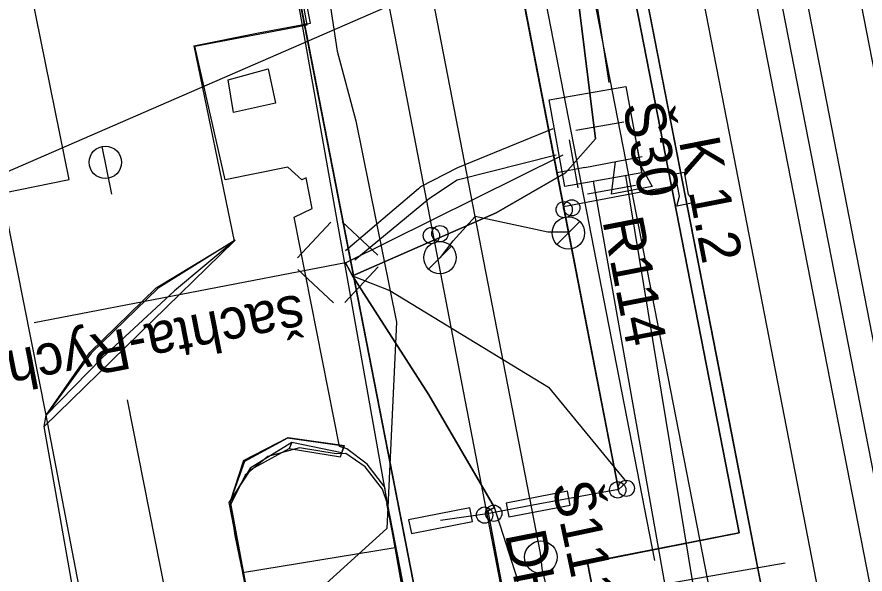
# Model space of a CAD drawing. Extents: x -545736 to -544888, y -1122892 to -1119128.
# Drawn here: x -545210.15 to -545184.08, y -1121953.8 to -1121936.67 of the extents above; entities that cross this region are included whole.
import ezdxf

# ---------------------------------------------------------------- set-up
doc = ezdxf.new("R2010")
doc.units = 0
for name, color, linetype in [('osvětlené plochy-hodnota-obrys', 7, 'Continuous'), ('Podbarveni_Nastupiste', 7, 'Continuous'), ('Podbarveni_Zastreseni_Pozemni', 7, 'Continuous'), ('Vrstva 1 - Koleje', 7, 'Continuous'), ('Vrstva 12', 7, 'Continuous'), ('Vrstva 14_zastreseni a nastupiste', 7, 'Continuous'), ('Vrstva 16_plochy', 7, 'Continuous'), ('Vrstva 17', 7, 'Continuous'), ('Vrstva 23', 7, 'Continuous'), ('Vrstva 28 - zabzar', 7, 'Continuous'), ('Vrstva 29 - sdelzar', 7, 'Continuous'), ('Vrstva 31', 7, 'Continuous'), ('Vrstva 33 - prvky sdelzar', 7, 'Continuous'), ('Vrstva 34', 7, 'Continuous'), ('Vrstva 35', 7, 'Continuous'), ('Vrstva 36', 7, 'Continuous'), ('Vrstva 4 - Teren - stezky - prechody - plochy', 7, 'Continuous'), ('Vrstva 42', 7, 'Continuous'), ('Vrstva 43', 7, 'Continuous'), ('Vrstva 44', 7, 'Continuous'), ('Vrstva 63', 7, 'Continuous')]:
    doc.layers.add(name, color=color, linetype=linetype)

msp = doc.modelspace()

# ---------------------------------------------------------------- linework, layer by layer
at = {"layer": 'osvětlené plochy-hodnota-obrys'}
msp.add_lwpolyline([(-545132.033, -1122317.745), (-545201.844, -1121957.194), (-545188.779, -1121954.655), (-545199.189, -1121901.389)], dxfattribs=at)
at = {"layer": 'Podbarveni_Nastupiste'}
for points in [[(-545187.251, -1121954.256), (-545197.191, -1121903.223), (-545206.675, -1121854.601), (-545216.326, -1121805.1), (-545225.795, -1121756.548), (-545231.585, -1121726.856)], [(-545208.774, -1121898.648), (-545202.231, -1121932.191), (-545198.773, -1121951.627)], [(-545198.773, -1121951.627), (-545191.691, -1121987.986), (-545182.222, -1122036.609), (-545172.438, -1122086.699), (-545162.999, -1122135.094), (-545153.274, -1122184.937), (-545142.505, -1122240.181), (-545142.306, -1122241.006)]]:
    msp.add_lwpolyline(points, dxfattribs=at)
at = {"layer": 'Podbarveni_Zastreseni_Pozemni'}
for p, q in [((-545192.608, -1121953.452), (-545187.955, -1121952.531)), ((-545192.612, -1121953.456), (-545192.608, -1121953.452))]:
    msp.add_line(p, q, dxfattribs=at)
for points in [[(-545187.955, -1121952.531), (-545197.581, -1121903.153), (-545207.045, -1121854.61), (-545216.686, -1121805.155), (-545226.175, -1121756.48), (-545231.934, -1121726.937)], [(-545208.774, -1121898.648), (-545202.231, -1121932.191), (-545197.881, -1121954.495)], [(-545183.384, -1122000.766), (-545186.124, -1121986.718), (-545192.612, -1121953.456)]]:
    msp.add_lwpolyline(points, dxfattribs=at)
at = {"layer": 'Vrstva 1 - Koleje'}
for points in [[(-545190.577, -1121928.351), (-545188.26, -1121940.241), (-545186.358, -1121950.008), (-545185.594, -1121953.976), (-545183.573, -1121964.342), (-545182.039, -1121972.211), (-545181.093, -1121977.067), (-545180.755, -1121978.799)], [(-545185.695, -1121928.619), (-545183.788, -1121938.392), (-545181.884, -1121948.167), (-545179.964, -1121958.007), (-545178.054, -1121967.8), (-545176.139, -1121977.604), (-545175.527, -1121980.741), (-545173.78, -1121989.695), (-545172.335, -1121997.117), (-545170.423, -1122006.932), (-545168.989, -1122014.279), (-545168.521, -1122016.677), (-545168.51, -1122016.735), (-545167.951, -1122019.64), (-545166.744, -1122025.83), (-545165.674, -1122031.328), (-545164.107, -1122039.354), (-545162.631, -1122046.922), (-545161.94, -1122050.474), (-545160.406, -1122058.34), (-545159.059, -1122065.253), (-545158.132, -1122070.002), (-545157.157, -1122074.99), (-545153.328, -1122094.638)]]:
    msp.add_lwpolyline(points, dxfattribs=at)
at = {"layer": 'Vrstva 12'}
for p, q in [((-545201.833, -1121949.62), (-545201.813, -1121949.606)), ((-545201.708, -1121949.757), (-545201.787, -1121949.944)), ((-545200.21, -1121950.201), (-545200.086, -1121949.848)), ((-545200.102, -1121949.872), (-545200.086, -1121949.848)), ((-545203.191, -1121950.312), (-545203.602, -1121951.576)), ((-545203.154, -1121950.338), (-545203.191, -1121950.312)), ((-545202.981, -1121950.545), (-545202.961, -1121950.588)), ((-545203.602, -1121951.576), (-545203.632, -1121951.602))]:
    msp.add_line(p, q, dxfattribs=at)
for points in [[(-545202.201, -1121939.318), (-545203.499, -1121939.609), (-545203.66, -1121938.6), (-545202.434, -1121938.261)], [(-545200.164, -1121950.073), (-545200.102, -1121949.872), (-545201.833, -1121949.62), (-545203.154, -1121950.338), (-545203.602, -1121951.576), (-545202.869, -1121955.481), (-545202.858, -1121955.552), (-545202.768, -1121956.297), (-545202.706, -1121956.342), (-545203.632, -1121951.602), (-545202.961, -1121950.588), (-545201.787, -1121949.944), (-545200.21, -1121950.201)]]:
    msp.add_lwpolyline(points, close=True, dxfattribs=at)
for points in [[(-545203.448, -1121943.531), (-545203.448, -1121943.531), (-545205.814, -1121945.005), (-545207.869, -1121947.007), (-545209.259, -1121948.92), (-545207.916, -1121946.985), (-545205.876, -1121944.997), (-545203.448, -1121943.531)], [(-545203.448, -1121943.531), (-545205.311, -1121945.094), (-545207.53, -1121947.153), (-545209.259, -1121948.92)], [(-545203.191, -1121950.312), (-545201.813, -1121949.606), (-545200.086, -1121949.848)], [(-545200.164, -1121950.073), (-545201.708, -1121949.757), (-545202.981, -1121950.545), (-545203.602, -1121951.576)]]:
    msp.add_lwpolyline(points, dxfattribs=at)
at = {"layer": 'Vrstva 14_zastreseni a nastupiste'}
msp.add_line((-545192.612, -1121953.456), (-545192.608, -1121953.452), dxfattribs=at)
for points in [[(-545187.955, -1121952.531), (-545197.617, -1121902.959), (-545207.134, -1121854.134), (-545216.759, -1121804.75), (-545226.215, -1121756.237), (-545235.472, -1121708.744), (-545235.481, -1121708.743), (-545226.175, -1121756.48), (-545216.686, -1121805.155), (-545207.045, -1121854.61), (-545197.581, -1121903.153), (-545187.955, -1121952.532)], [(-545197.884, -1121954.495), (-545202.248, -1121932.117), (-545208.774, -1121898.648), (-545208.774, -1121898.648), (-545202.231, -1121932.191), (-545197.881, -1121954.495)], [(-545187.251, -1121954.256), (-545188.391, -1121948.391), (-545190.303, -1121938.581), (-545192.214, -1121928.77)], [(-545187.245, -1121954.27), (-545188.385, -1121948.405), (-545190.297, -1121938.595), (-545192.208, -1121928.784)], [(-545198.773, -1121951.627), (-545198.793, -1121951.631), (-545197.668, -1121957.434), (-545195.753, -1121967.224), (-545195.374, -1121969.187), (-545193.463, -1121979.015), (-545191.56, -1121988.764), (-545189.639, -1121998.596), (-545187.731, -1122008.385), (-545185.791, -1122018.31), (-545183.91, -1122027.957), (-545182.003, -1122037.734), (-545180.094, -1122047.536), (-545178.189, -1122057.285), (-545176.275, -1122067.11), (-545174.372, -1122076.877), (-545172.469, -1122086.648)], [(-545198.773, -1121951.627), (-545197.637, -1121957.485), (-545195.722, -1121967.275), (-545195.343, -1121969.238), (-545193.432, -1121979.066), (-545191.529, -1121988.815), (-545189.608, -1121998.647), (-545187.7, -1122008.436), (-545185.76, -1122018.361), (-545183.879, -1122028.008), (-545181.972, -1122037.785), (-545180.063, -1122047.587), (-545178.158, -1122057.336), (-545176.244, -1122067.161), (-545174.341, -1122076.928), (-545172.438, -1122086.699)], [(-545192.612, -1121953.456), (-545191.169, -1121953.17), (-545187.955, -1121952.531), (-545187.955, -1121952.532), (-545192.608, -1121953.452)], [(-545138.248, -1122232.184), (-545147.826, -1122183.078), (-545157.444, -1122133.764), (-545166.966, -1122084.945), (-545176.486, -1122036.133), (-545186.124, -1121986.718), (-545192.612, -1121953.456)], [(-545192.608, -1121953.452), (-545186.031, -1121987.181), (-545176.442, -1122036.358), (-545166.925, -1122085.165), (-545157.406, -1122133.984), (-545147.796, -1122183.265), (-545138.257, -1122232.186)]]:
    msp.add_lwpolyline(points, dxfattribs=at)
for centre in [(-545193.33, -1121942.594), (-545193.096, -1121942.538), (-545197.412, -1121943.393), (-545197.15, -1121943.334), (-545191.684, -1121951.215), (-545191.422, -1121951.166), (-545195.776, -1121951.99), (-545195.495, -1121951.933)]:
    msp.add_circle(centre, 0.25, dxfattribs=at)
at = {"layer": 'Vrstva 16_plochy'}
for points in [[(-545198.772, -1121951.626), (-545198.846, -1121951.132), (-545199.386, -1121950.421), (-545200.013, -1121949.951), (-545200.237, -1121949.881), (-545201.629, -1121942.821), (-545201.074, -1121942.555), (-545201.266, -1121941.615), (-545201.396, -1121941.674), (-545201.822, -1121941.29), (-545203.751, -1121941.677), (-545204.686, -1121937.57), (-545201.23, -1121936.907), (-545202.884, -1121927.9), (-545206.444, -1121928.549), (-545207.952, -1121920.539), (-545208.311, -1121918.602), (-545208.161, -1121917.406), (-545206.384, -1121916.999), (-545207.447, -1121909.391), (-545205.017, -1121908.98)], [(-545187.251, -1121954.256), (-545188.391, -1121948.391), (-545190.303, -1121938.581), (-545192.214, -1121928.77)], [(-545172.438, -1122086.699), (-545174.341, -1122076.928), (-545176.244, -1122067.161), (-545178.158, -1122057.336), (-545180.063, -1122047.587), (-545181.972, -1122037.785), (-545183.879, -1122028.008), (-545185.76, -1122018.361), (-545187.7, -1122008.436), (-545189.608, -1121998.647), (-545191.529, -1121988.815), (-545193.432, -1121979.066), (-545195.343, -1121969.238), (-545195.722, -1121967.275), (-545197.637, -1121957.485), (-545198.773, -1121951.627)]]:
    msp.add_lwpolyline(points, dxfattribs=at)
at = {"layer": 'Vrstva 17'}
for p, q in [((-545204.716, -1121937.552), (-545202.733, -1121937.156)), ((-545204.716, -1121937.552), (-545203.473, -1121943.564)), ((-545203.473, -1121943.564), (-545209.317, -1121949.263))]:
    msp.add_line(p, q, dxfattribs=at)
msp.add_lwpolyline([(-545202.733, -1121937.156), (-545201.132, -1121936.862), (-545202.894, -1121927.887), (-545206.444, -1121928.549)], dxfattribs=at)
at = {"layer": 'Vrstva 23'}
for p, q in [((-545203.434, -1121965.339), (-545206.752, -1121948.44)), ((-545196.366, -1122015.979), (-545209.259, -1121948.92))]:
    msp.add_line(p, q, dxfattribs=at)
msp.add_lwpolyline([(-545199.383, -1122000.837), (-545202.829, -1121983.168), (-545208.015, -1121956.626), (-545209.317, -1121949.263), (-545209.259, -1121948.92), (-545210.612, -1121942.089), (-545208.554, -1121941.671), (-545213.053, -1121919.523), (-545225.888, -1121922.128)], dxfattribs=at)
at = {"layer": 'Vrstva 28 - zabzar'}
msp.add_lwpolyline([(-545184.11, -1121980.06), (-545190.31, -1121981.59), (-545194.52, -1121959.69), (-545194.75, -1121953.99), (-545195.47, -1121951.76), (-545197.49, -1121948.29), (-545199.84, -1121944.63), (-545200.05, -1121944.23), (-545193.363, -1121940.913)], dxfattribs=at)
at = {"layer": 'Vrstva 29 - sdelzar'}
for p, q in [((-545192.69, -1121941.3), (-545193.55, -1121941.46)), ((-545190.48, -1121941.96), (-545193.35, -1121942.51)), ((-545191.66, -1121951.2), (-545191.41, -1121950.98)), ((-545195.72, -1121951.89), (-545195.47, -1121951.76)), ((-545195.72, -1121951.89), (-545195.7, -1121951.95)), ((-545170.88, -1122078.92), (-545195.7, -1121951.95))]:
    msp.add_line(p, q, dxfattribs=at)
for points in [[(-545238.22, -1121711.14), (-545234.93, -1121728.12), (-545231.3, -1121746.83), (-545227.7, -1121765.38), (-545223.97, -1121784.59), (-545220.37, -1121803.18), (-545216.73, -1121821.93), (-545213.13, -1121840.52), (-545209.71, -1121858.15), (-545206.26, -1121875.91), (-545203.14, -1121892.01), (-545203.04, -1121892.5), (-545200.17, -1121907.31), (-545196.87, -1121924.33), (-545191.66, -1121951.2)], [(-545191.66, -1121951.2), (-545193.35, -1121942.51), (-545235.14, -1121727)], [(-545225.37, -1121777.4), (-545216.94, -1121820.87), (-545205.32, -1121880.79), (-545201.375, -1121901.125), (-545191.66, -1121951.2), (-545194.13, -1121951.65), (-545195.7, -1121951.95), (-545197.13, -1121952.16)], [(-545141.59, -1122228.62), (-545144.06, -1122216.03), (-545147.37, -1122199.08), (-545150.66, -1122182.28), (-545153.96, -1122165.39), (-545157.26, -1122148.51), (-545160.57, -1122131.6), (-545163.89, -1122114.65), (-545167.28, -1122097.28), (-545170.47, -1122080.98), (-545173.77, -1122064.13), (-545177.12, -1122047.02), (-545180.38, -1122030.35), (-545180.51, -1122029.8), (-545183.68, -1122013.47), (-545187, -1121996.49), (-545190.31, -1121979.56), (-545193.64, -1121962.56), (-545195.18, -1121954.67), (-545202.44, -1121916.94)], [(-545195.67, -1121951.86), (-545195.68, -1121951.84), (-545195.47, -1121951.76)], [(-545144.46, -1122213.97), (-545194.03, -1121960.56), (-545195.67, -1121951.86)]]:
    msp.add_lwpolyline(points, dxfattribs=at)
at = {"layer": 'Vrstva 31'}
msp.add_line((-545200.05, -1121944.23), (-545209.63, -1121946.08), dxfattribs=at)
for points in [[(-545200.05, -1121944.23), (-545199.84, -1121944.63), (-545195.42, -1121942.69), (-545193.29, -1121941.46), (-545192.37, -1121940.42), (-545194.56, -1121922.72)], [(-545194.56, -1121922.72), (-545192.37, -1121940.42), (-545193.29, -1121941.46), (-545195.42, -1121942.69), (-545199.84, -1121944.63)], [(-545199.84, -1121944.63), (-545195.42, -1121942.69), (-545193.29, -1121941.46), (-545192.37, -1121940.42)], [(-545200.05, -1121944.23), (-545199.84, -1121944.63)], [(-545195.47, -1121951.76), (-545197.49, -1121948.29), (-545199.84, -1121944.63)], [(-545199.84, -1121944.63), (-545198.69, -1121945.08), (-545193.81, -1121948.05), (-545191.41, -1121950.98)], [(-545199.84, -1121944.63), (-545197.49, -1121948.29), (-545195.47, -1121951.76), (-545195.72, -1121951.89)], [(-545199.84, -1121944.63), (-545198.69, -1121945.08), (-545193.81, -1121948.05), (-545191.41, -1121950.98), (-545191.66, -1121951.2)], [(-545199.84, -1121944.63), (-545198.69, -1121945.08), (-545193.81, -1121948.05), (-545191.41, -1121950.98), (-545191.66, -1121951.2)], [(-545199.84, -1121944.63), (-545197.49, -1121948.29), (-545195.47, -1121951.76)]]:
    msp.add_lwpolyline(points, dxfattribs=at)
at = {"layer": 'Vrstva 33 - prvky sdelzar'}
for p, q in [((-545192.69, -1121941.3), (-545190.931, -1121940.959)), ((-545190.48, -1121941.96), (-545189.852, -1121941.838))]:
    msp.add_line(p, q, dxfattribs=at)
for points in [[(-545191.119, -1121940.995), (-545190.622, -1121941.877), (-545191.879, -1121942.121), (-545191.748, -1121941.117)], [(-545189.918, -1121941.496), (-545189.646, -1121941.443)], [(-545189.785, -1121942.18), (-545189.918, -1121941.496)], [(-545189.646, -1121941.443), (-545189.513, -1121942.127)], [(-545189.867, -1121942.484), (-545189.785, -1121942.18)], [(-545189.513, -1121942.127), (-545189.318, -1121942.377)], [(-545189.318, -1121942.377), (-545189.867, -1121942.484)]]:
    msp.add_lwpolyline(points, dxfattribs=at)
for points in [[(-545193.147, -1121951.679), (-545193.231, -1121951.254), (-545195.112, -1121951.622), (-545195.029, -1121952.047)], [(-545196.147, -1121952.189), (-545196.231, -1121951.764), (-545198.112, -1121952.132), (-545198.029, -1121952.557)]]:
    msp.add_lwpolyline(points, close=True, dxfattribs=at)
at = {"layer": 'Vrstva 34'}
for p, q in [((-545192.97, -1121940.154), (-545191.494, -1121939.888)), ((-545191.203, -1121940.089), (-545190.937, -1121941.565)), ((-545192.905, -1121941.921), (-545193.171, -1121940.445)), ((-545191.138, -1121941.856), (-545192.614, -1121942.122)), ((-545200.153, -1121942.972), (-545199.057, -1121943.997)), ((-545201.531, -1121944.08), (-545200.506, -1121942.984)), ((-545200.423, -1121945.458), (-545201.519, -1121944.433)), ((-545199.045, -1121944.35), (-545200.07, -1121945.446))]:
    msp.add_line(p, q, dxfattribs=at)
at = {"layer": 'Vrstva 35'}
for points in [[(-545191.944, -1121938.683), (-545195.619, -1121914.8)], [(-545193.678, -1121940.11), (-545196.608, -1121941.311), (-545197.744, -1121941.897), (-545197.809, -1121941.954), (-545200.056, -1121943.857)], [(-545193.578, -1121940.922), (-545196.616, -1121941.684), (-545197.468, -1121942.254), (-545199.768, -1121944.147)], [(-545184.906, -1121977.25), (-545187.86, -1121963.28), (-545191.432, -1121941.547)], [(-545185.989, -1121977.456), (-545188.56, -1121963.51), (-545192.424, -1121941.723)]]:
    msp.add_lwpolyline(points, dxfattribs=at)
at = {"layer": 'Vrstva 36'}
msp.add_lwpolyline([(-545193.79, -1121939.22), (-545191.43, -1121938.81), (-545190.94, -1121941.46), (-545193.31, -1121941.88)], close=True, dxfattribs=at)
for points in [[(-545193.79, -1121939.22), (-545191.43, -1121938.81), (-545190.94, -1121941.46), (-545193.31, -1121941.88), (-545193.79, -1121939.22)], [(-545191.43, -1121938.81), (-545191.43, -1121938.81)], [(-545193.79, -1121939.22), (-545193.79, -1121939.22)], [(-545190.94, -1121941.46), (-545190.94, -1121941.46)], [(-545193.31, -1121941.88), (-545193.31, -1121941.88)]]:
    msp.add_lwpolyline(points, dxfattribs=at)
at = {"layer": 'Vrstva 4 - Teren - stezky - prechody - plochy'}
msp.add_line((-545191.456, -1121954.323), (-545186.532, -1121953.455), dxfattribs=at)
for points in [[(-545168.578, -1122024.344), (-545174.628, -1121993.69), (-545179.747, -1121967.537), (-545186.346, -1121933.692), (-545192.541, -1121901.817), (-545198.719, -1121870.005), (-545203.649, -1121844.746)], [(-545168.578, -1122024.344), (-545170.138, -1122024.197), (-545176.818, -1121990.692), (-545181.528, -1121966.416), (-545187.742, -1121934.55), (-545194.141, -1121901.786), (-545200.392, -1121870.233)], [(-545187.245, -1121954.27), (-545188.385, -1121948.405), (-545190.297, -1121938.595), (-545192.208, -1121928.784)], [(-545191.56, -1121988.764), (-545193.463, -1121979.015), (-545195.374, -1121969.187), (-545195.753, -1121967.224), (-545197.668, -1121957.434), (-545198.305, -1121954.272), (-545198.526, -1121952.983), (-545198.777, -1121951.611), (-545198.918, -1121951.188), (-545199.444, -1121950.503), (-545200.046, -1121950.093), (-545200.336, -1121950.101), (-545201.47, -1121949.918), (-545202.442, -1121950.189), (-545203.141, -1121950.759), (-545203.59, -1121951.67), (-545203.458, -1121952.616), (-545203.219, -1121953.758), (-545202.906, -1121955.205), (-545202.565, -1121956.903)], [(-545203.219, -1121953.758), (-545198.526, -1121952.983)]]:
    msp.add_lwpolyline(points, dxfattribs=at)
at = {"layer": 'Vrstva 42'}
for points in [[(-545203.534, -1121918.02), (-545203.421, -1121918.681), (-545202.986, -1121920.789), (-545201.955, -1121926.819), (-545200.311, -1121937.722)], [(-545200.311, -1121937.722), (-545199.74, -1121939.864), (-545198.486, -1121946.055), (-545198.782, -1121952.405), (-545201.965, -1121955.297), (-545200.981, -1121959.998), (-545197.52, -1121977.94), (-545189.718, -1122017.188), (-545181.934, -1122057.193)]]:
    msp.add_lwpolyline(points, dxfattribs=at)
at = {"layer": 'Vrstva 43'}
for p, q in [((-545207.239, -1121942.118), (-545207.537, -1121940.65)), ((-545193.553, -1121943.664), (-545192.848, -1121942.96)), ((-545197.502, -1121944.42), (-545196.797, -1121943.716))]:
    msp.add_line(p, q, dxfattribs=at)
msp.add_lwpolyline([(-545221.64, -1121793.845), (-545216.677, -1121819.304), (-545215.137, -1121827.201), (-545204.798, -1121880.11), (-545202.406, -1121892.353), (-545195.991, -1121925.439), (-545195.251, -1121929.242), (-545194.988, -1121930.593), (-545190.551, -1121953.388)], dxfattribs=at)
for centre, radius in [((-545207.438, -1121941.138), 0.498), ((-545193.2, -1121943.312), 0.498), ((-545197.149, -1121944.069), 0.498), ((-545194.046, -1121953.285), 0.5)]:
    msp.add_circle(centre, radius, dxfattribs=at)
at = {"layer": 'Vrstva 44'}
for points in [[(-545180.662, -1122034.333), (-545184.014, -1122019.078), (-545187.459, -1122002.038), (-545190.967, -1121984.029), (-545191.024, -1121983.688), (-545190.997, -1121983.256), (-545190.532, -1121983.18), (-545188.483, -1121982.815), (-545188.273, -1121982.75), (-545188.289, -1121982.487), (-545190.918, -1121967.576), (-545192.659, -1121959.264), (-545194.003, -1121953.627), (-545194.032, -1121953.413), (-545194.056, -1121953.159), (-545196.062, -1121942.809), (-545198.906, -1121928.142)], [(-545176.233, -1121989.498), (-545187.573, -1121931.466), (-545187.78, -1121931.163)], [(-545197.15, -1121944.068), (-545197.134, -1121944.067), (-545196.741, -1121943.55), (-545196.062, -1121942.809)], [(-545193.201, -1121943.312), (-545193.206, -1121943.284), (-545193.832, -1121943.284), (-545196.062, -1121942.809)]]:
    msp.add_lwpolyline(points, dxfattribs=at)
at = {"layer": 'Vrstva 63'}
msp.add_line((-545174.192, -1121925.66), (-545267.199, -1121966.112), dxfattribs=at)

# ---------------------------------------------------------------- texts
at = {"layer": 'Vrstva 33 - prvky sdelzar'}
for s, rotation, p in [('K 1.2', 280.9763, (-545189.806, -1121940.477)), ('R114', 280.9763, (-545192.159, -1121942.936)), ('DHM23', 281.0678, (-545195.153, -1121952.572))]:
    msp.add_text(s, height=1.25, rotation=rotation, dxfattribs=at).set_placement(p)
at = {"layer": 'Vrstva 34'}
for s, rotation, p in [('Š30', 280.2458, (-545191.533, -1121939.374)), ('šachta-Rychlozboží', 191.0299, (-545201.438, -1121945.188))]:
    msp.add_text(s, height=1.25, rotation=rotation, dxfattribs=at).set_placement(p)
at = {"layer": 'Vrstva 43'}
msp.add_text('Š111', height=1.25, rotation=281.9566, dxfattribs=at).set_placement((-545193.709, -1121951.062))

doc.saveas('drawing.dxf')
